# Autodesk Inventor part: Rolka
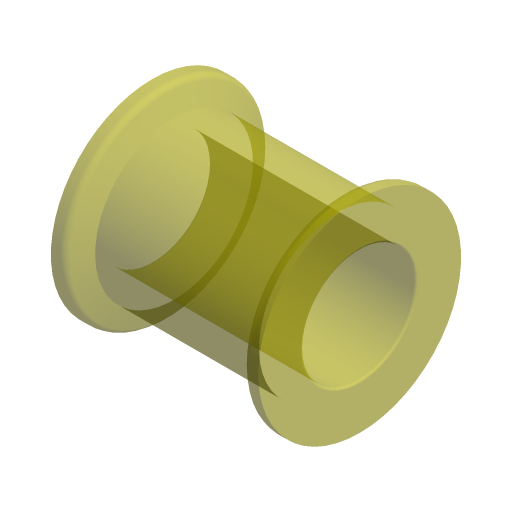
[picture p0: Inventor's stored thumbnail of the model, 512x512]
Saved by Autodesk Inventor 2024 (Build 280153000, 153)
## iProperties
Company: ATC
Shininess: 20.0
Length Units: 11269
Angle Units: 11279
Time Units: 11290
Mass Units: 11283
Length Display Precision: 3
Angle Display Precision: 2
Compacted: True
Created: 2023-03
Part Number: Rolka
Document SubType Name: Modeling
Designer: Andrzej Jaskulski
Density: 1 g/cm^3
Material: Ogólny
Appearance: Yellow(Clear)
Checked By: A.J.
Engr Approved By: Andrzej Jaskulski
Mfg Approved By: Andrzej Jaskulski
Authority: A.J.
Density: 0.0
Volumn: 0.0
Area: 0.0
PropertySet Name: Model Information
Control State: 0
Master: False
Checked Out: False
Title: A.J.: Kurs R2024-MEP
Author: Andrzej Jaskulski
Revision Number: 1/24
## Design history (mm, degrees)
node "Revolution1" dims "d7" = 90 deg
node "Fillet1" dims "d8" = 1.5
node "Fillet2" dims "d11" = 0.5
node "Bryła1"
node "Korpusy bryłowe"
node "Korpusy powierzchniowe"
sketch "Sketch1"
  geometry: L1 (20, -40)-(66, -40); L2 (66, -40)-(66, -30); L3 (66, -30)-(63, -30); L4 (63, -30)-(61.18, -35); L5 (61.18, -35)-(24.82, -35); L6 (24.82, -35)-(23, -30); L7 (23, -30)-(20, -30); L8 (20, -30)-(20, -40); L9 (14, -52.5)-(73, -52.5)
  constraints: 18 end point, 4 parallel, 3 equal length, 2 perpendicular, 1 horizontal, 1 other
  dimensions: "d0" = 10 distance of L1.end L2.end; "d1" = 5 distance between parallel lines of L1 L5; "d2" = 3 distance of L2.end L3.end; "d4" = 110 deg angle of L5 L4; "d5" = 46 distance of L2.end L7.end (derived); "d6" = 12.5 distance between parallel lines of L9 L1
